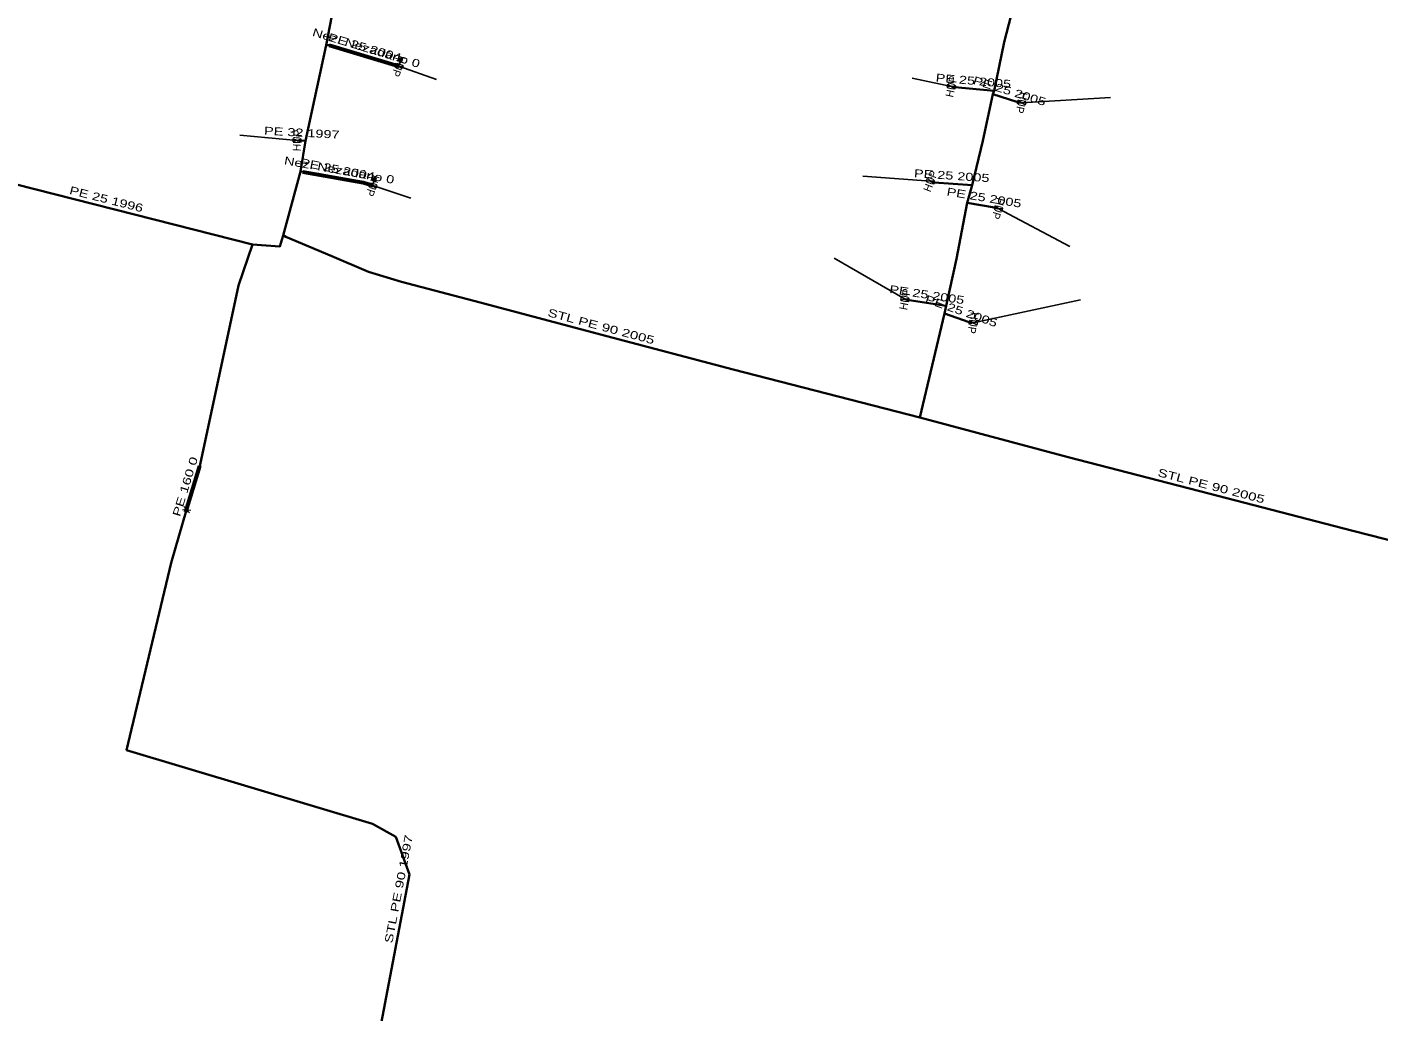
# Model space of a CAD drawing. Extents: x -737484 to -734496, y -1033882 to -1030666.
# Drawn here: x -735749 to -735580.1, y -1032174.7 to -1032051.6 of the extents above; entities that cross this region are included whole.
import ezdxf
from ezdxf.enums import TextEntityAlignment as Align

# ---------------------------------------------------------------- set-up
doc = ezdxf.new("R2010")
doc.units = 0
doc.header["$LTSCALE"] = 0.4
for name, color, linetype, lineweight in [('1', 7, 'Continuous', 13), ('18', 7, 'Continuous', 60), ('22', 7, 'Continuous', 25), ('5', 7, 'Continuous', 35), ('7', 7, 'Continuous', 35)]:
    doc.layers.add(name, color=color, linetype=linetype, lineweight=lineweight)
doc.layers.add('2', color=7, linetype='Continuous')

msp = doc.modelspace()

# ---------------------------------------------------------------- linework, layer by layer
at = {"layer": '1'}
for p, q in [((-735702.284, -1032055.927), (-735702.17, -1032055.596)), ((-735702.543, -1032056.447), (-735702.38, -1032055.974)), ((-735705.799, -1032071.382), (-735705.644, -1032070.906)), ((-735705.549, -1032070.858), (-735705.441, -1032070.525)), ((-735729.398, -1032111.488), (-735728.675, -1032112.285)), ((-735729.574, -1032111.847), (-735728.499, -1032111.926))]:
    msp.add_line(p, q, dxfattribs=at)
for points in [[(-735702.217, -1032055.501), (-735702.359, -1032055.452), (-735702.522, -1032055.925), (-735702.38, -1032055.974)], [(-735702.217, -1032055.501), (-735702.075, -1032055.55), (-735702.238, -1032056.023), (-735702.38, -1032055.974)], [(-735702.194, -1032055.549), (-735702.123, -1032055.573), (-735702.262, -1032055.975), (-735702.333, -1032055.951)], [(-735702.005, -1032056.42), (-735702.135, -1032056.798), (-735702.95, -1032056.095), (-735703.08, -1032056.473)], [(-735634.015, -1032059.083), (-735633.932, -1032058.692), (-735633.037, -1032059.291), (-735632.954, -1032058.9)], [(-735624.193, -1032060.921), (-735624.276, -1032061.312), (-735625.171, -1032060.713), (-735625.254, -1032061.104)], [(-735715.733, -1032065.907), (-735715.712, -1032065.508), (-735714.735, -1032065.959), (-735714.714, -1032065.56)], [(-735705.489, -1032070.43), (-735705.632, -1032070.384), (-735705.787, -1032070.86), (-735705.644, -1032070.906)], [(-735705.489, -1032070.43), (-735705.347, -1032070.477), (-735705.501, -1032070.952), (-735705.644, -1032070.906)], [(-735705.466, -1032070.478), (-735705.395, -1032070.501), (-735705.526, -1032070.905), (-735705.597, -1032070.882)], [(-735636.635, -1032070.832), (-735636.492, -1032070.459), (-735635.701, -1032071.19), (-735635.558, -1032070.817)], [(-735705.261, -1032071.346), (-735705.385, -1032071.726), (-735706.212, -1032071.037), (-735706.336, -1032071.417)], [(-735627.094, -1032074.188), (-735627.204, -1032074.573), (-735628.055, -1032073.912), (-735628.165, -1032074.297)], [(-735639.802, -1032085.68), (-735639.726, -1032085.288), (-735638.821, -1032085.871), (-735638.745, -1032085.479)], [(-735630.246, -1032088.412), (-735630.309, -1032088.807), (-735631.234, -1032088.256), (-735631.297, -1032088.651)]]:
    msp.add_lwpolyline(points, close=True, dxfattribs=at)
at = {"layer": '18'}
for p, q in [((-735711.236, -1032053.816), (-735702.542, -1032056.447)), ((-735729.151, -1032112.16), (-735727.391, -1032106.42))]:
    msp.add_line(p, q, dxfattribs=at)
msp.add_lwpolyline([(-735714.538, -1032069.637), (-735706.967, -1032070.991), (-735705.798, -1032071.381)], dxfattribs=at)
at = {"layer": '22'}
for p, q in [((-735702.543, -1032056.447), (-735697.83, -1032058.116)), ((-735633.485, -1032058.992), (-735638.379, -1032057.966)), ((-735624.724, -1032061.013), (-735613.603, -1032060.366)), ((-735715.23, -1032065.73), (-735722.395, -1032065.053)), ((-735636.097, -1032070.825), (-735644.54, -1032070.181)), ((-735705.799, -1032071.382), (-735701.044, -1032072.927)), ((-735627.63, -1032074.243), (-735618.691, -1032078.977)), ((-735639.274, -1032085.58), (-735648.147, -1032080.45)), ((-735630.772, -1032088.532), (-735617.352, -1032085.672))]:
    msp.add_line(p, q, dxfattribs=at)
at = {"layer": '5'}
for points in [[(-735716.966, -1032077.63), (-735714.831, -1032069.632), (-735714.19, -1032065.79), (-735711.61, -1032053.828), (-735710.45, -1032047.75), (-735709.025, -1032041.048), (-735706.569, -1032030.37), (-735704.884, -1032022.631), (-735704.42, -1032020.57), (-735703.406, -1032015.99), (-735701.946, -1032008.423), (-735700.92, -1032004.53), (-735700.089, -1032000), (-735700.065, -1031999.868), (-735697.165, -1031986.58), (-735695.932, -1031980.417), (-735694.12, -1031971.69), (-735694.03, -1031971.502), (-735693.24, -1031967.62), (-735692.89, -1031965.568), (-735691.099, -1031960.091)], [(-735637.43, -1032100.371), (-735634.359, -1032087.377), (-735634.124, -1032086.384), (-735632.85, -1032080.524), (-735631.513, -1032073.536), (-735630.893, -1032071.306), (-735629.552, -1032065.783), (-735628.293, -1032059.963), (-735628.159, -1032059.511), (-735626.899, -1032053.435), (-735625.486, -1032047.96)], [(-735727.61, -1032264.16), (-735720.34, -1032249.21), (-735714.85, -1032237.63), (-735708.3, -1032218.96), (-735713.1, -1032215.9), (-735706.04, -1032182.91), (-735701.19, -1032157.47), (-735702.91, -1032152.78), (-735705.8, -1032151.16), (-735736.55, -1032141.95), (-735730.97, -1032118.51), (-735729.04, -1032111.89), (-735727.47, -1032106.8), (-735722.56, -1032083.87), (-735720.82, -1032078.73), (-735717.39, -1032078.97), (-735716.966, -1032077.63)], [(-735716.966, -1032077.63), (-735716.872, -1032077.671), (-735716.647, -1032077.766), (-735710.883, -1032080.187), (-735706.337, -1032082.153), (-735702.203, -1032083.413), (-735692.361, -1032085.975), (-735676.526, -1032090.198), (-735660.751, -1032094.344), (-735637.43, -1032100.371)], [(-735637.43, -1032100.371), (-735618.914, -1032105.299), (-735601.321, -1032109.863), (-735583.316, -1032114.512), (-735565.066, -1032119.183)]]:
    msp.add_lwpolyline(points, dxfattribs=at)
at = {"layer": '7'}
msp.add_line((-735714.19, -1032065.79), (-735715.224, -1032065.734), dxfattribs=at)
for points in [[(-735711.61, -1032053.828), (-735711.237, -1032053.817), (-735710.304, -1032054.089), (-735709.712, -1032054.278), (-735703.684, -1032056.043), (-735702.543, -1032056.447)], [(-735628.159, -1032059.511), (-735633.07, -1032059.079), (-735633.485, -1032058.992)], [(-735628.293, -1032059.963), (-735625.298, -1032060.894), (-735624.724, -1032061.013)], [(-735720.82, -1032078.73), (-735755.42, -1032069.96), (-735754.4, -1032067.708)], [(-735714.831, -1032069.632), (-735714.539, -1032069.638), (-735713.811, -1032069.754), (-735713.907, -1032069.756), (-735712.555, -1032069.897), (-735706.978, -1032070.999), (-735705.799, -1032071.382)], [(-735630.893, -1032071.306), (-735635.661, -1032070.992), (-735636.097, -1032070.825)], [(-735631.513, -1032073.536), (-735628.108, -1032074.103), (-735627.63, -1032074.243)], [(-735634.124, -1032086.384), (-735638.767, -1032085.679), (-735639.274, -1032085.58)], [(-735634.359, -1032087.377), (-735631.283, -1032088.455), (-735630.772, -1032088.532)]]:
    msp.add_lwpolyline(points, dxfattribs=at)

# ---------------------------------------------------------------- texts
at = {"layer": '18'}
for s, rotation, width, p in [('Nez. Nezadáno 0', 343.163, 1.35, (-735706.7438, -1032054.6524)), ('Nez. Nezadáno 0', 349.86, 1.35, (-735710.0575, -1032069.9295)), ('PE 160 0', 72.953, 1.4, (-735728.7489, -1032109.1431))]:
    msp.add_text(s, height=1, rotation=rotation, dxfattribs=dict(at, width=width)).set_placement(p, align=Align.CENTER)
at = {"layer": '2', "width": 0.95}
for rotation, p in [(251, (-735703.015, -1032056.2837)), (78, (-735632.9952, -1032059.0955)), (258, (-735625.2128, -1032060.9085)), (87, (-735714.7245, -1032065.7597)), (252, (-735706.274, -1032071.227)), (69, (-735635.6297, -1032071.0037)), (254, (-735628.1098, -1032074.1047)), (79, (-735638.7829, -1032085.6749)), (261, (-735631.2655, -1032088.4533))]:
    msp.add_text('HUP', height=1, rotation=rotation, dxfattribs=at).set_placement(p, align=Align.CENTER)
at = {"layer": '5', "width": 1.4}
for s, rotation, p in [('STL PE 90 2005', 345.067, (-735677.3788, -1032089.4519)), ('STL PE 90 2005', 345.522, (-735601.148, -1032109.3909)), ('STL PE 90 1997', 79.206, (-735702.0648, -1032159.3931))]:
    msp.add_text(s, height=1, rotation=rotation, dxfattribs=at).set_placement(p, align=Align.CENTER)
at = {"layer": '7', "width": 1.35}
for s, rotation, p in [('PE 25 2004', 343.68, (-735706.9195, -1032054.5735)), ('PE 25 2005', 354.973, (-735630.7813, -1032058.7775)), ('PE 25 2005', 342.732, (-735626.3664, -1032060.0375)), ('PE 32 1997', 356.9, (-735714.679, -1032065.2625)), ('PE 25 2004', 348.822, (-735710.2799, -1032069.8363)), ('PE 25 2005', 356.232, (-735633.4764, -1032070.6344)), ('PE 25 1996', 345.777, (-735739.1948, -1032073.5562)), ('PE 25 2005', 350.546, (-735629.4821, -1032073.3663)), ('PE 25 2005', 351.366, (-735636.6256, -1032085.4974)), ('PE 25 2005', 340.687, (-735632.4114, -1032087.5291))]:
    msp.add_text(s, height=1, rotation=rotation, dxfattribs=at).set_placement(p, align=Align.CENTER)

doc.saveas('drawing.dxf')
